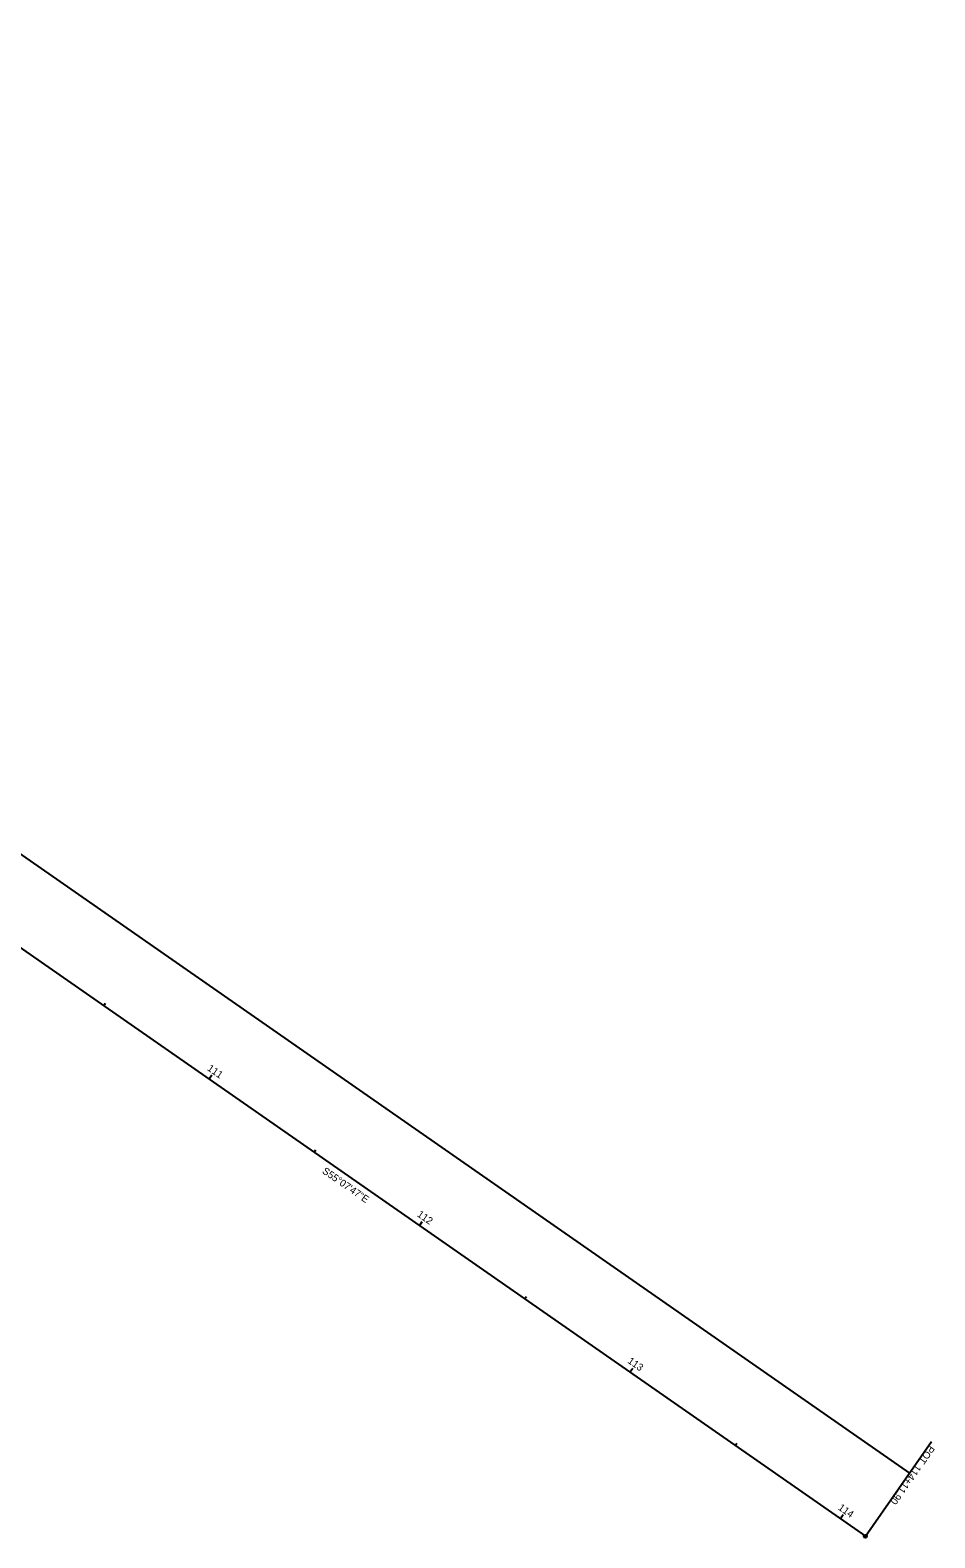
# Model space of a CAD drawing. Extents: x 2318731 to 2320621, y 732958 to 734198.
# Drawn here: x 2320268 to 2320621, y 732958 to 733546 of the extents above; entities that cross this region are included whole.
import ezdxf

# ---------------------------------------------------------------- set-up
doc = ezdxf.new("R2010")
doc.units = 0
for name, color, linetype in [('RW_X_CL_100_Bearings', 7, 'Continuous'), ('RW_X_CL_100_Cardinal_Points', 7, 'Continuous'), ('RW_X_CL_100_Stations', 7, 'Continuous'), ('RW_X_CL_500_Bearings', 7, 'Continuous'), ('RW_X_CL_500_Cardinal_Points', 7, 'Continuous'), ('RW_X_CL_500_Stations', 7, 'Continuous'), ('V-SURV-PARL-LINE', 7, 'Continuous'), ('V-SURV-RWAY', 7, 'Continuous')]:
    doc.layers.add(name, color=color, linetype=linetype)

msp = doc.modelspace()

# ---------------------------------------------------------------- linework, layer by layer
at = {"layer": 'RW_X_CL_100_Cardinal_Points'}
msp.add_line((2320594.07, 732958.73), (2320619.8, 732995.65), dxfattribs=at)
msp.add_circle((2320594.07, 732958.73), 0.6, dxfattribs=at)
at = {"layer": 'RW_X_CL_100_Stations'}
for p, q in [((2320297.15, 733165.63), (2320297.84, 733166.62)), ((2320338.17, 733137.05), (2320339.32, 733138.69)), ((2320379.19, 733108.46), (2320379.88, 733109.45)), ((2320420.22, 733079.88), (2320421.36, 733081.52)), ((2320461.24, 733051.29), (2320461.93, 733052.27)), ((2320502.26, 733022.7), (2320503.41, 733024.34)), ((2320543.28, 732994.12), (2320543.97, 732995.1)), ((2320584.31, 732965.53), (2320585.45, 732967.17))]:
    msp.add_line(p, q, dxfattribs=at)
at = {"layer": 'RW_X_CL_500_Cardinal_Points'}
msp.add_line((2320594.07, 732958.73), (2320619.8, 732995.65), dxfattribs=at)
msp.add_circle((2320594.07, 732958.73), 0.6, dxfattribs=at)
at = {"layer": 'RW_X_CL_500_Stations'}
for p, q in [((2320338.17, 733137.05), (2320338.86, 733138.03)), ((2320420.22, 733079.88), (2320420.9, 733080.86)), ((2320502.26, 733022.7), (2320502.95, 733023.69)), ((2320584.31, 732965.53), (2320584.99, 732966.52))]:
    msp.add_line(p, q, dxfattribs=at)
at = {"layer": 'V-SURV-PARL-LINE'}
msp.add_line((2319803.49, 733546.2), (2320611.23, 732983.34), dxfattribs=at)
at = {"layer": 'V-SURV-RWAY'}
msp.add_line((2320193.75, 733237.69), (2320594.07, 732958.73), dxfattribs=at)

# ---------------------------------------------------------------- texts
at = {"layer": 'RW_X_CL_100_Bearings'}
msp.add_text('S55°07\'47"E', height=2.8, rotation=325.12986, dxfattribs=at).set_placement((2320382.08, 733100.6))
at = {"layer": 'RW_X_CL_100_Cardinal_Points'}
for s, p in [('POT', (2320619.03, 732994.46)), ('114+11.90', (2320613.81, 732986.97))]:
    msp.add_text(s, height=2.8, rotation=235.12986, dxfattribs=at).set_placement(p)
at = {"layer": 'RW_X_CL_100_Stations'}
for s, p in [('111', (2320337.29, 733140.71)), ('112', (2320419.08, 733083.72)), ('113', (2320501.16, 733026.58)), ('114', (2320583.2, 732969.35))]:
    msp.add_text(s, height=2.8, rotation=325.12986, dxfattribs=at).set_placement(p)
at = {"layer": 'RW_X_CL_500_Bearings'}
msp.add_text('S55°07\'47"E', height=2.8, rotation=325.12986, dxfattribs=at).set_placement((2320382.08, 733100.6))
at = {"layer": 'RW_X_CL_500_Cardinal_Points'}
for s, p in [('POT', (2320619.03, 732994.46)), ('114+11.90', (2320613.81, 732986.97))]:
    msp.add_text(s, height=2.8, rotation=235.12986, dxfattribs=at).set_placement(p)

doc.saveas('drawing.dxf')
